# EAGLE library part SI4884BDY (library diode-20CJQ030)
Vishay Siliconix N-Channel 30-V (D-S) MOSFET FEATURES: TrenchFET Power MOSFET PWM Optimized Please send any comments to: messi@users.sourceforge.net
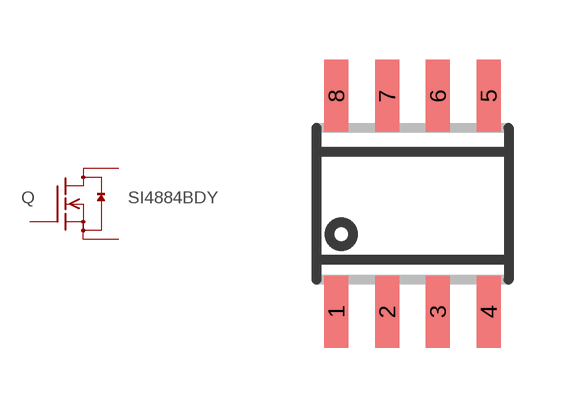
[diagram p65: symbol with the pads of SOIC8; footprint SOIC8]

Designator prefix Q

## SI4884BDY  [SOIC8]
1  S  pas
2  S  pas
3  S  pas
4  G  pas
5  D  pas
6  D  pas
7  D  pas
8  D  pas

## Footprint SOIC8 (pad centres in mm)
Small Outline IC
smd 0.6 x 1.8: 1 -1.905,-2.7; 2 -0.635,-2.7; 3 0.635,-2.7; 4 1.905,-2.7; 5 1.905,2.7; 6 0.635,2.7; 7 -0.635,2.7; 8 -1.905,2.7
